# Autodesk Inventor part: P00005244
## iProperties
Shininess: 64.0
Length Units: 11269
Angle Units: 11279
Time Units: 11290
Mass Units: 11283
Length Display Precision: 3
Angle Display Precision: 2
Compacted: True
Part Number: P00005244
Document SubType Name: Modeling
Created: 2004-01
Material: Stahl (schweißbar)
Designer: Mittelmeyer
Manufacturer: Standard
Standards Organization: Custom
Density: 0.0
Volumn: 0.0
Area: 0.0
PropertySet Name: Model Information
Control State: 0
Master: False
Checked Out: False
Author: Mittelmeyer
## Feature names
1. Basis1
